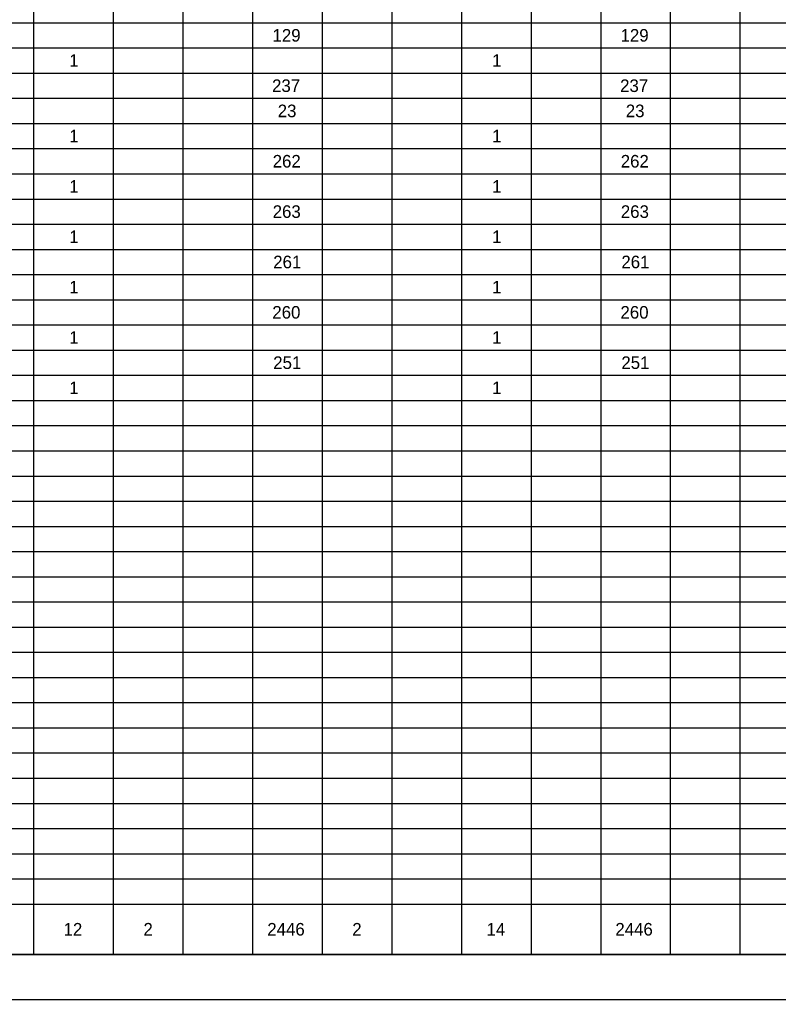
# Model space of a CAD drawing. Extents: x 0 to 34, y 0 to 22.
# Drawn here: x 17.13 to 25.56, y 0 to 10.89 of the extents above; entities that cross this region are included whole.
import ezdxf

# ---------------------------------------------------------------- set-up
doc = ezdxf.new("R2010")
doc.units = 0
for name, color, linetype in [('SH_Border', 7, 'Continuous'), ('SH_Cut_Line', 7, 'Continuous'), ('SH_Text', 7, 'Continuous')]:
    doc.layers.add(name, color=color, linetype=linetype)

msp = doc.modelspace()

# ---------------------------------------------------------------- linework, layer by layer
at = {"layer": 'SH_Border'}
msp.add_lwpolyline([(1.5, 21.5), (33.5, 21.5), (33.5, 0.5), (1.5, 0.5)], close=True, dxfattribs=at)
at = {"layer": 'SH_Cut_Line'}
msp.add_lwpolyline([(0, 0), (34, 0), (34, 22), (0, 22)], close=True, dxfattribs=at)
at = {"layer": 'SH_Text'}
for p, q in [((17.279, 21.5), (17.279, 0.5)), ((18.168, 21.5), (18.168, 0.5)), ((18.942, 21.5), (18.942, 0.5)), ((19.716, 21.5), (19.716, 0.5)), ((20.491, 21.5), (20.491, 0.5)), ((21.265, 21.5), (21.265, 0.5)), ((22.039, 21.5), (22.039, 0.5)), ((22.813, 21.5), (22.813, 0.5)), ((23.587, 21.5), (23.587, 0.5)), ((24.361, 21.5), (24.361, 0.5)), ((25.135, 21.5), (25.135, 0.5)), ((1.5, 10.86), (31.724, 10.86)), ((1.5, 10.58), (31.724, 10.58)), ((1.5, 10.3), (31.724, 10.3)), ((1.5, 10.02), (31.724, 10.02)), ((1.5, 9.74), (31.724, 9.74)), ((1.5, 9.46), (31.724, 9.46)), ((1.5, 9.18), (31.724, 9.18)), ((1.5, 8.9), (31.724, 8.9)), ((1.5, 8.62), (31.724, 8.62)), ((1.5, 8.34), (31.724, 8.34)), ((1.5, 8.06), (31.724, 8.06)), ((1.5, 7.78), (31.724, 7.78)), ((1.5, 7.5), (31.724, 7.5)), ((1.5, 7.22), (31.724, 7.22)), ((1.5, 6.94), (31.724, 6.94)), ((1.5, 6.66), (31.724, 6.66)), ((1.5, 6.38), (31.724, 6.38)), ((1.5, 6.1), (31.724, 6.1)), ((1.5, 5.82), (31.724, 5.82)), ((1.5, 5.54), (31.724, 5.54)), ((1.5, 5.26), (31.724, 5.26)), ((1.5, 4.98), (31.724, 4.98)), ((1.5, 4.7), (31.724, 4.7)), ((1.5, 4.42), (31.724, 4.42)), ((1.5, 4.14), (31.724, 4.14)), ((1.5, 3.86), (31.724, 3.86)), ((1.5, 3.58), (31.724, 3.58)), ((1.5, 3.3), (31.724, 3.3)), ((1.5, 3.02), (31.724, 3.02)), ((1.5, 2.74), (31.724, 2.74)), ((1.5, 2.46), (31.724, 2.46)), ((1.5, 2.18), (31.724, 2.18)), ((1.5, 1.9), (31.724, 1.9)), ((1.5, 1.62), (31.724, 1.62)), ((1.5, 1.34), (31.724, 1.34)), ((1.5, 1.06), (31.724, 1.06)), ((1.5, 0.5), (31.724, 0.5))]:
    msp.add_line(p, q, dxfattribs=at)

# ---------------------------------------------------------------- texts
for s, p in [('129', (19.938, 10.65)), ('129', (23.808, 10.65)), ('1', (17.678, 10.37)), ('1', (22.38, 10.37)), ('237', (19.933, 10.09)), ('237', (23.803, 10.09)), ('23', (19.996, 9.81)), ('23', (23.866, 9.81)), ('1', (17.678, 9.53)), ('1', (22.38, 9.53)), ('262', (19.94, 9.25)), ('262', (23.81, 9.25)), ('1', (17.678, 8.97)), ('1', (22.38, 8.97)), ('263', (19.94, 8.69)), ('263', (23.811, 8.69)), ('1', (17.678, 8.41)), ('1', (22.38, 8.41)), ('261', (19.946, 8.13)), ('261', (23.817, 8.13)), ('1', (17.678, 7.85)), ('1', (22.38, 7.85)), ('260', (19.936, 7.57)), ('260', (23.807, 7.57)), ('1', (17.678, 7.29)), ('1', (22.38, 7.29)), ('251', (19.946, 7.01)), ('251', (23.817, 7.01)), ('1', (17.678, 6.73)), ('1', (22.38, 6.73)), ('12', (17.615, 0.71)), ('2', (18.503, 0.71)), ('2446', (19.88, 0.71)), ('2', (20.825, 0.71)), ('14', (22.318, 0.71)), ('2446', (23.75, 0.71))]:
    msp.add_text(s, height=0.14, dxfattribs=at).set_placement(p)

doc.saveas('drawing.dxf')
